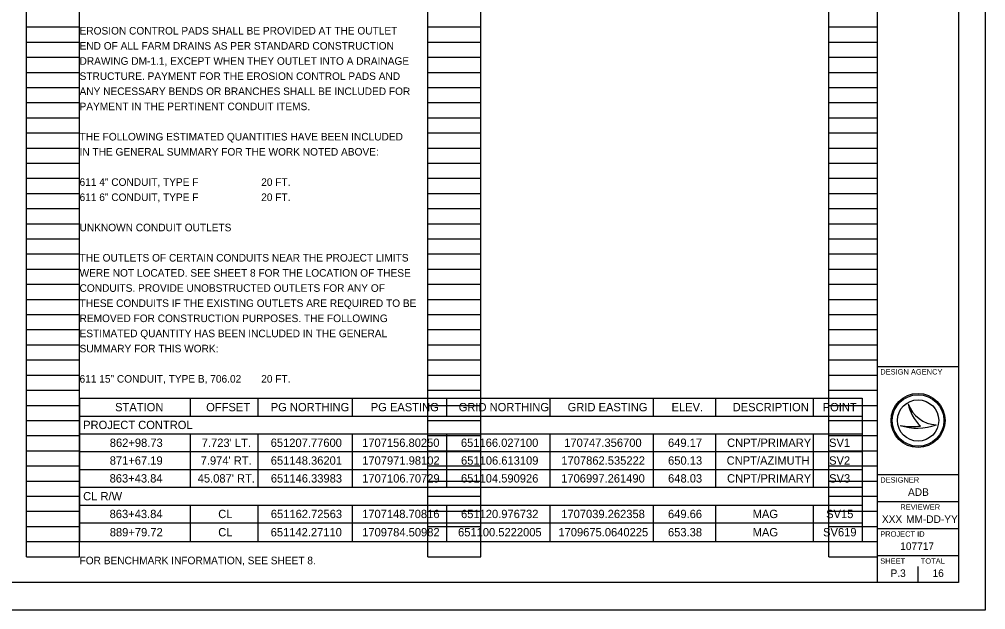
# Model space of a CAD drawing. Extents: x 37.8 to 71.8, y 8.7 to 30.7.
# Drawn here: x 53.88 to 71.76, y 8.67 to 19.59 of the extents above; entities that cross this region are included whole.
import ezdxf

# ---------------------------------------------------------------- set-up
doc = ezdxf.new("R2010")
doc.units = 0
for name, color, linetype in [('Default', 7, 'Continuous'), ('SH_Border', 7, 'Continuous'), ('SH_Cut_Line', 7, 'Continuous'), ('SH_Data', 7, 'Continuous'), ('SH_Text', 7, 'Continuous')]:
    doc.layers.add(name, color=color, linetype=linetype)

msp = doc.modelspace()

# ---------------------------------------------------------------- linework, layer by layer
at = {"layer": 'Default'}
for p, q in [((54.999, 12.584), (69.477, 12.584)), ((54.999, 12.584), (54.999, 9.932)), ((57.042, 12.584), (57.042, 12.254)), ((58.294, 12.584), (58.294, 12.254)), ((60.039, 12.584), (60.039, 12.254)), ((61.785, 12.584), (61.785, 12.254)), ((63.696, 12.584), (63.696, 12.254)), ((65.607, 12.584), (65.607, 12.254)), ((66.759, 12.584), (66.759, 12.254)), ((68.571, 12.584), (68.571, 12.254)), ((69.477, 12.584), (69.477, 9.932)), ((54.999, 12.254), (69.477, 12.254)), ((54.999, 11.925), (69.477, 11.925)), ((57.042, 11.925), (57.042, 10.937)), ((58.294, 11.925), (58.294, 10.937)), ((60.039, 11.925), (60.039, 10.937)), ((61.785, 11.925), (61.785, 10.937)), ((63.696, 11.925), (63.696, 10.937)), ((65.607, 11.925), (65.607, 10.937)), ((66.759, 11.925), (66.759, 10.937)), ((68.571, 11.925), (68.571, 10.937)), ((54.999, 11.595), (69.477, 11.595)), ((54.999, 11.266), (69.477, 11.266)), ((54.999, 10.937), (69.477, 10.937)), ((54.999, 10.607), (69.477, 10.607)), ((57.042, 10.607), (57.042, 9.932)), ((58.294, 10.607), (58.294, 9.932)), ((60.039, 10.607), (60.039, 9.932)), ((61.785, 10.607), (61.785, 9.932)), ((63.696, 10.607), (63.696, 9.932)), ((65.607, 10.607), (65.607, 9.932)), ((66.759, 10.607), (66.759, 9.932)), ((68.571, 10.607), (68.571, 9.932)), ((54.999, 10.278), (69.477, 10.278)), ((54.999, 9.932), (69.477, 9.932))]:
    msp.add_line(p, q, dxfattribs=at)
at = {"layer": 'SH_Border'}
for p, q in [((69.759, 9.172), (69.759, 30.172)), ((69.759, 13.172), (71.259, 13.172)), ((69.759, 11.172), (71.259, 11.172)), ((69.759, 10.672), (71.259, 10.672)), ((69.759, 10.172), (71.259, 10.172)), ((69.759, 9.672), (71.259, 9.672))]:
    msp.add_line(p, q, dxfattribs=at)
msp.add_lwpolyline([(39.259, 30.172), (71.259, 30.172), (71.259, 9.172), (39.259, 9.172)], close=True, dxfattribs=at)
at = {"layer": 'SH_Cut_Line'}
msp.add_lwpolyline([(37.759, 8.672), (71.759, 8.672), (71.759, 30.672), (37.759, 30.672)], close=True, dxfattribs=at)
at = {"layer": 'SH_Data'}
for p, q in [((54.019, 9.652), (54.019, 29.812)), ((54.999, 9.652), (54.999, 29.812)), ((61.439, 9.652), (61.439, 29.812)), ((62.419, 9.652), (62.419, 29.812)), ((68.859, 9.652), (68.859, 29.812)), ((69.759, 9.652), (69.759, 29.812)), ((54.019, 19.452), (54.999, 19.452)), ((61.439, 19.452), (62.419, 19.452)), ((68.859, 19.452), (69.759, 19.452)), ((54.019, 19.172), (54.999, 19.172)), ((61.439, 19.172), (62.419, 19.172)), ((68.859, 19.172), (69.759, 19.172)), ((54.019, 18.892), (54.999, 18.892)), ((61.439, 18.892), (62.419, 18.892)), ((68.859, 18.892), (69.759, 18.892)), ((54.019, 18.612), (54.999, 18.612)), ((61.439, 18.612), (62.419, 18.612)), ((68.859, 18.612), (69.759, 18.612)), ((54.019, 18.332), (54.999, 18.332)), ((61.439, 18.332), (62.419, 18.332)), ((68.859, 18.332), (69.759, 18.332)), ((54.019, 18.052), (54.999, 18.052)), ((61.439, 18.052), (62.419, 18.052)), ((68.859, 18.052), (69.759, 18.052)), ((54.019, 17.772), (54.999, 17.772)), ((61.439, 17.772), (62.419, 17.772)), ((68.859, 17.772), (69.759, 17.772)), ((54.019, 17.492), (54.999, 17.492)), ((61.439, 17.492), (62.419, 17.492)), ((68.859, 17.492), (69.759, 17.492)), ((54.019, 17.212), (54.999, 17.212)), ((61.439, 17.212), (62.419, 17.212)), ((68.859, 17.212), (69.759, 17.212)), ((54.019, 16.932), (54.999, 16.932)), ((61.439, 16.932), (62.419, 16.932)), ((68.859, 16.932), (69.759, 16.932)), ((54.019, 16.652), (54.999, 16.652)), ((61.439, 16.652), (62.419, 16.652)), ((68.859, 16.652), (69.759, 16.652)), ((54.019, 16.372), (54.999, 16.372)), ((61.439, 16.372), (62.419, 16.372)), ((68.859, 16.372), (69.759, 16.372)), ((54.019, 16.092), (54.999, 16.092)), ((61.439, 16.092), (62.419, 16.092)), ((68.859, 16.092), (69.759, 16.092)), ((54.019, 15.812), (54.999, 15.812)), ((61.439, 15.812), (62.419, 15.812)), ((68.859, 15.812), (69.759, 15.812)), ((54.019, 15.532), (54.999, 15.532)), ((61.439, 15.532), (62.419, 15.532)), ((68.859, 15.532), (69.759, 15.532)), ((54.019, 15.252), (54.999, 15.252)), ((61.439, 15.252), (62.419, 15.252)), ((68.859, 15.252), (69.759, 15.252)), ((54.019, 14.972), (54.999, 14.972)), ((61.439, 14.972), (62.419, 14.972)), ((68.859, 14.972), (69.759, 14.972)), ((54.019, 14.692), (54.999, 14.692)), ((61.439, 14.692), (62.419, 14.692)), ((68.859, 14.692), (69.759, 14.692)), ((54.019, 14.412), (54.999, 14.412)), ((61.439, 14.412), (62.419, 14.412)), ((68.859, 14.412), (69.759, 14.412)), ((54.019, 14.132), (54.999, 14.132)), ((61.439, 14.132), (62.419, 14.132)), ((68.859, 14.132), (69.759, 14.132)), ((54.019, 13.852), (54.999, 13.852)), ((61.439, 13.852), (62.419, 13.852)), ((68.859, 13.852), (69.759, 13.852)), ((54.019, 13.572), (54.999, 13.572)), ((61.439, 13.572), (62.419, 13.572)), ((68.859, 13.572), (69.759, 13.572)), ((54.019, 13.292), (54.999, 13.292)), ((61.439, 13.292), (62.419, 13.292)), ((68.859, 13.292), (69.759, 13.292)), ((54.019, 13.012), (54.999, 13.012)), ((61.439, 13.012), (62.419, 13.012)), ((68.859, 13.012), (69.759, 13.012)), ((54.019, 12.732), (54.999, 12.732)), ((61.439, 12.732), (62.419, 12.732)), ((68.859, 12.732), (69.759, 12.732)), ((54.019, 12.452), (54.999, 12.452)), ((61.439, 12.452), (62.419, 12.452)), ((68.859, 12.452), (69.759, 12.452)), ((70.327, 12.482), (70.327, 12.482)), ((54.019, 12.172), (54.999, 12.172)), ((61.439, 12.172), (62.419, 12.172)), ((68.859, 12.172), (69.759, 12.172)), ((70.509, 12.172), (70.509, 12.172)), ((70.177, 12.081), (70.177, 12.081)), ((70.847, 12.09), (70.847, 12.09)), ((54.019, 11.892), (54.999, 11.892)), ((61.439, 11.892), (62.419, 11.892)), ((68.859, 11.892), (69.759, 11.892)), ((54.019, 11.612), (54.999, 11.612)), ((61.439, 11.612), (62.419, 11.612)), ((68.859, 11.612), (69.759, 11.612)), ((54.019, 11.332), (54.999, 11.332)), ((61.439, 11.332), (62.419, 11.332)), ((68.859, 11.332), (69.759, 11.332)), ((54.019, 11.052), (54.999, 11.052)), ((61.439, 11.052), (62.419, 11.052)), ((68.859, 11.052), (69.759, 11.052)), ((54.019, 10.772), (54.999, 10.772)), ((61.439, 10.772), (62.419, 10.772)), ((68.859, 10.772), (69.759, 10.772)), ((54.019, 10.492), (54.999, 10.492)), ((61.439, 10.492), (62.419, 10.492)), ((68.859, 10.492), (69.759, 10.492)), ((54.019, 10.212), (54.999, 10.212)), ((61.439, 10.212), (62.419, 10.212)), ((68.859, 10.212), (69.759, 10.212)), ((54.019, 9.932), (54.999, 9.932)), ((61.439, 9.932), (62.419, 9.932)), ((68.859, 9.932), (69.759, 9.932)), ((54.019, 9.652), (54.999, 9.652)), ((61.439, 9.652), (62.419, 9.652)), ((68.859, 9.652), (69.759, 9.652)), ((70.134, 9.347), (70.134, 9.347)), ((70.509, 9.172), (70.509, 9.472))]:
    msp.add_line(p, q, dxfattribs=at)
for radius in [0.5, 0.477, 0.477, 0.382]:
    msp.add_circle((70.509, 12.172), radius, dxfattribs=at)
for centre, radius, start, end in [((70.875, 12.67), 0.58, 198.9257, 198.9319), ((71.106, 12.642), 0.796, 191.6379, 191.6421), ((70.875, 12.67), 0.58, 198.9319, 267.1657), ((71.106, 12.642), 0.796, 191.6421, 226.0947), ((70.499, 13.042), 1.013, 251.4576, 290.0832), ((70.407, 13.326), 1.266, 259.4964, 259.4995), ((70.499, 13.042), 1.013, 251.4527, 251.4576), ((70.407, 13.326), 1.266, 259.4995, 276.6672)]:
    msp.add_arc(centre, radius, start, end, dxfattribs=at)

# ---------------------------------------------------------------- texts
at = {"layer": 'Default'}
for s, p in [('STATION', (55.657, 12.342)), ('OFFSET', (57.341, 12.342)), ('PG NORTHING', (58.535, 12.342)), ('PG EASTING', (60.385, 12.342)), ('GRID NORTHING', (62.012, 12.342)), ('GRID EASTING', (64.027, 12.342)), ('ELEV.', (65.949, 12.342)), ('DESCRIPTION', (67.08, 12.342)), ('POINT', (68.745, 12.342)), ('PROJECT CONTROL', (55.065, 12.013)), ('862+98.73', (55.558, 11.683)), ("7.723' LT.", (57.259, 11.683)), ('651207.77600', (58.534, 11.683)), ('1707156.80250', (60.225, 11.683)), ('651166.027100', (62.053, 11.683)), ('170747.356700', (63.964, 11.683)), ('649.17', (65.884, 11.683)), ('CNPT/PRIMARY', (66.976, 11.683)), ('SV1', (68.863, 11.683)), ('871+67.19', (55.557, 11.354)), ("7.974' RT.", (57.239, 11.354)), ('651148.36201', (58.536, 11.354)), ('1707971.98102', (60.227, 11.354)), ('651106.613109', (62.055, 11.354)), ('1707862.535222', (63.911, 11.354)), ('650.13', (65.885, 11.354)), ('CNPT/AZIMUTH', (66.968, 11.354)), ('SV2', (68.863, 11.354)), ('863+43.84', (55.555, 11.024)), ("45.087' RT.", (57.184, 11.024)), ('651146.33983', (58.537, 11.024)), ('1707106.70729', (60.227, 11.024)), ('651104.590926', (62.054, 11.024)), ('1706997.261490', (63.908, 11.024)), ('648.03', (65.885, 11.024)), ('CNPT/PRIMARY', (66.976, 11.024)), ('SV3', (68.864, 11.024)), ('CL R/W', (55.065, 10.695)), ('863+43.84', (55.555, 10.366)), ('CL', (57.564, 10.366)), ('651162.72563', (58.537, 10.366)), ('1707148.70816', (60.225, 10.366)), ('651120.976732', (62.055, 10.366)), ('1707039.262358', (63.909, 10.366)), ('649.66', (65.883, 10.366)), ('MAG', (67.449, 10.366)), ('SV15', (68.809, 10.366)), ('889+79.72', (55.558, 10.028)), ('CL', (57.564, 10.028)), ('651142.27110', (58.534, 10.028)), ('1709784.50982', (60.227, 10.028)), ('651100.5222005', (62, 10.028)), ('1709675.0640225', (63.856, 10.028)), ('653.38', (65.883, 10.028)), ('MAG', (67.449, 10.028)), ('SV619', (68.752, 10.028))]:
    msp.add_text(s, height=0.154, dxfattribs=at).set_placement(p)
at = {"layer": 'SH_Data'}
for s, height, p in [('DESIGN AGENCY', 0.1, (69.809, 13.022)), ('DESIGNER', 0.1, (69.809, 11.022)), ('ADB', 0.14, (70.323, 10.777)), ('REVIEWER', 0.1, (70.181, 10.522)), ('XXX', 0.14, (69.84, 10.277)), ('MM-DD-YY', 0.14, (70.287, 10.277)), ('PROJECT ID', 0.1, (69.809, 10.022)), ('107717', 0.14, (70.179, 9.777)), ('SHEET', 0.1, (69.809, 9.522)), ('TOTAL', 0.1, (70.559, 9.522)), ('P.3', 0.14, (70, 9.277)), ('16', 0.14, (70.777, 9.277))]:
    msp.add_text(s, height=height, dxfattribs=at).set_placement(p)
at = {"layer": 'SH_Text'}
for s, p in [('EROSION CONTROL PADS SHALL BE PROVIDED AT THE OUTLET', (54.999, 19.312)), ('END OF ALL FARM DRAINS AS PER STANDARD CONSTRUCTION', (54.999, 19.032)), ('DRAWING DM-1.1, EXCEPT WHEN THEY OUTLET INTO A DRAINAGE', (54.999, 18.752)), ('STRUCTURE. PAYMENT FOR THE EROSION CONTROL PADS AND', (54.999, 18.472)), ('ANY NECESSARY BENDS OR BRANCHES SHALL BE INCLUDED FOR', (54.999, 18.192)), ('PAYMENT IN THE PERTINENT CONDUIT ITEMS.', (54.999, 17.912)), ('THE FOLLOWING ESTIMATED QUANTITIES HAVE BEEN INCLUDED', (54.999, 17.352)), ('IN THE GENERAL SUMMARY FOR THE WORK NOTED ABOVE:', (54.999, 17.072)), ('611 4" CONDUIT, TYPE F', (54.999, 16.512)), ('20 FT.', (58.359, 16.512)), ('611 6" CONDUIT, TYPE F', (54.999, 16.232)), ('20 FT.', (58.359, 16.232)), ('UNKNOWN CONDUIT OUTLETS', (54.999, 15.672)), ('THE OUTLETS OF CERTAIN CONDUITS NEAR THE PROJECT LIMITS', (54.999, 15.112)), ('WERE NOT LOCATED. SEE SHEET 8 FOR THE LOCATION OF THESE', (54.999, 14.832)), ('CONDUITS. PROVIDE UNOBSTRUCTED OUTLETS FOR ANY OF', (54.999, 14.552)), ('THESE CONDUITS IF THE EXISTING OUTLETS ARE REQUIRED TO BE', (54.999, 14.272)), ('REMOVED FOR CONSTRUCTION PURPOSES. THE FOLLOWING', (54.999, 13.992)), ('ESTIMATED QUANTITY HAS BEEN INCLUDED IN THE GENERAL', (54.999, 13.712)), ('SUMMARY FOR THIS WORK: ', (54.999, 13.432)), ('611 15" CONDUIT, TYPE B, 706.02', (54.999, 12.872)), ('20 FT.', (58.359, 12.872)), ('FOR BENCHMARK INFORMATION, SEE SHEET 8.', (54.999, 9.512))]:
    msp.add_text(s, height=0.14, dxfattribs=at).set_placement(p)

doc.saveas('drawing.dxf')
